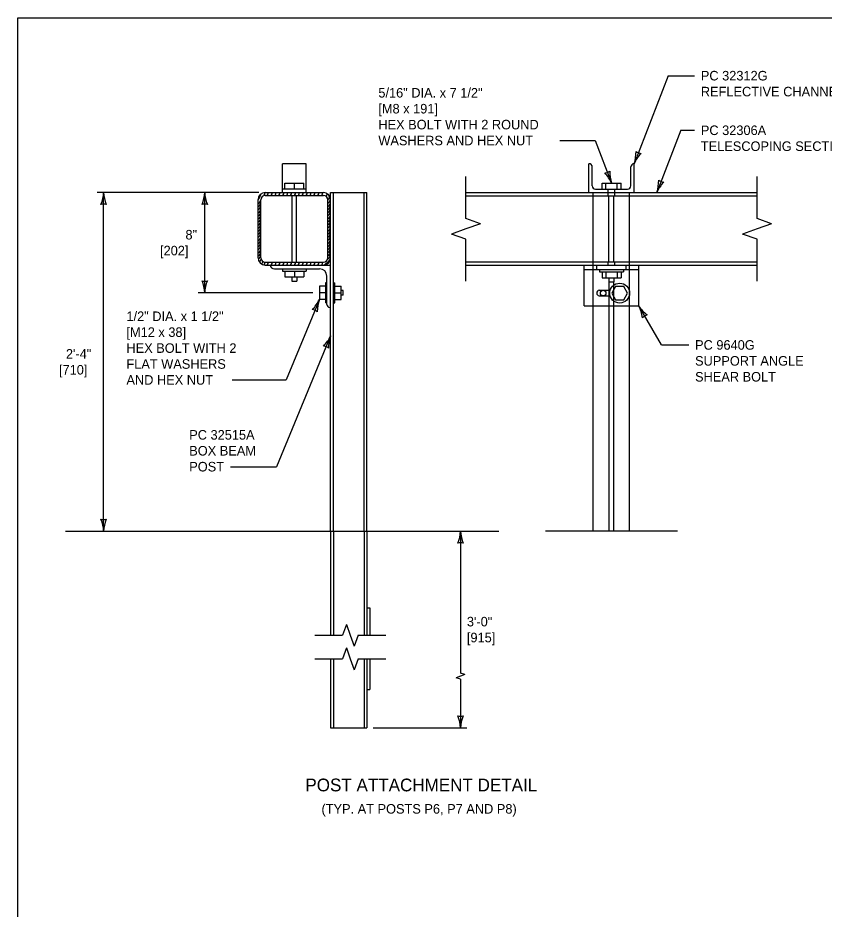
# Model space of a CAD drawing. Extents: x 49991.4 to 50021, y 49987.6 to 50011.4.
# Drawn here: x 49999.38 to 50004.45, y 49993.4 to 49999 of the extents above; entities that cross this region are included whole.
import ezdxf

# ---------------------------------------------------------------- set-up
doc = ezdxf.new("R2010")
doc.units = 0
for name, color, linetype in [('Level 1', 7, 'Continuous'), ('Level 2', 7, 'Continuous'), ('Level 3', 7, 'Continuous'), ('Level 4', 7, 'Continuous'), ('Level 6', 7, 'Continuous')]:
    doc.layers.add(name, color=color, linetype=linetype)

msp = doc.modelspace()

# ---------------------------------------------------------------- linework, layer by layer
at = {"layer": 'Level 1'}
for p, q in [((50001.0456, 49997.9021), (50001.0456, 49998.0824)), ((50001.1955, 49998.0824), (50001.0456, 49998.0824)), ((50001.1955, 49997.9021), (50001.1955, 49998.0824)), ((50002.9708, 49997.902), (50002.9708, 49998.0824)), ((50003.2538, 49998.0824), (50003.2546, 49998.0824)), ((50003.2546, 49997.902), (50003.2546, 49998.0824)), ((50002.9916, 49997.9428), (50002.9916, 49998.0624)), ((50003.2338, 49997.9428), (50003.2338, 49998.0624)), ((50003.0116, 49997.9228), (50003.2138, 49997.9228)), ((50003.0528, 49997.9228), (50003.0528, 49997.9596)), ((50003.0528, 49997.9596), (50003.1726, 49997.9596)), ((50003.0772, 49997.9228), (50003.0772, 49997.9596)), ((50003.148, 49997.9228), (50003.148, 49997.9596)), ((50003.1726, 49997.9228), (50003.1726, 49997.9596)), ((50000.9377, 49997.9021), (50001.3025, 49997.9021)), ((50000.9378, 49997.8839), (50001.3026, 49997.8839)), ((50001.1057, 49997.4643), (50001.1057, 49997.8839)), ((50001.1344, 49997.4643), (50001.1344, 49997.8839)), ((50001.3481, 49995.7737), (50001.3481, 49997.9021)), ((50001.3481, 49997.9021), (50001.5762, 49997.9021)), ((50001.3664, 49995.7737), (50001.3664, 49997.9021)), ((50001.558, 49995.7737), (50001.558, 49997.9021)), ((50001.5762, 49995.7737), (50001.5762, 49997.9021)), ((50002.198, 49997.902), (50004.0265, 49997.902)), ((50000.8921, 49997.4915), (50000.8921, 49997.8565)), ((50000.9104, 49997.4917), (50000.9104, 49997.8565)), ((50001.33, 49997.4917), (50001.33, 49997.8565)), ((50000.9377, 49997.4459), (50001.3481, 49997.4459)), ((50000.9378, 49997.4643), (50001.3026, 49997.4643)), ((50000.9954, 49997.4223), (50001.279, 49997.4223)), ((50001.0456, 49997.4223), (50001.0456, 49997.4081)), ((50001.1948, 49997.4223), (50001.1948, 49997.4081)), ((50002.198, 49997.4448), (50004.0265, 49997.4448)), ((50002.9406, 49997.1894), (50002.9406, 49997.4448)), ((50002.9406, 49997.4174), (50003.2834, 49997.4174)), ((50003.0373, 49997.4174), (50003.0373, 49997.4033)), ((50003.1868, 49997.4174), (50003.1868, 49997.4033)), ((50003.2834, 49997.1894), (50003.2834, 49997.4448)), ((50001.0456, 49997.4081), (50001.1948, 49997.4081)), ((50001.061, 49997.4081), (50001.061, 49997.3714)), ((50001.061, 49997.3714), (50001.1806, 49997.3714)), ((50001.1202, 49997.4081), (50001.1202, 49997.3714)), ((50001.1806, 49997.4081), (50001.1806, 49997.3714)), ((50001.3246, 49997.1981), (50001.3246, 49997.3767)), ((50003.0373, 49997.4033), (50003.1868, 49997.4033)), ((50003.0528, 49997.4033), (50003.0528, 49997.3664)), ((50003.0528, 49997.3664), (50003.1726, 49997.3664)), ((50003.0772, 49997.4033), (50003.0772, 49997.3664)), ((50003.148, 49997.4033), (50003.148, 49997.3664)), ((50003.1726, 49997.4033), (50003.1726, 49997.3664)), ((50001.3152, 49997.3133), (50001.2773, 49997.3133)), ((50001.2773, 49997.3133), (50001.2773, 49997.2295)), ((50001.3152, 49997.3335), (50001.3152, 49997.2091)), ((50001.3246, 49997.3335), (50001.3152, 49997.3335)), ((50001.3664, 49997.3335), (50001.3756, 49997.3335)), ((50001.3756, 49997.2091), (50001.3756, 49997.3335)), ((50001.3756, 49997.3133), (50001.4135, 49997.3133)), ((50001.4135, 49997.2295), (50001.4135, 49997.3133)), ((50001.3152, 49997.2713), (50001.2773, 49997.2713)), ((50001.3756, 49997.2713), (50001.4135, 49997.2713)), ((50001.427, 49997.2861), (50001.4135, 49997.2861)), ((50001.427, 49997.2569), (50001.4135, 49997.2569)), ((50001.427, 49997.2569), (50001.427, 49997.2861)), ((50003.035, 49997.2871), (50003.1037, 49997.2871)), ((50003.0352, 49997.2523), (50003.1037, 49997.2523)), ((50001.3152, 49997.2295), (50001.2773, 49997.2295)), ((50001.3246, 49997.2091), (50001.3152, 49997.2091)), ((50001.3664, 49997.2091), (50001.3756, 49997.2091)), ((50001.3756, 49997.2295), (50001.4135, 49997.2295)), ((50002.9406, 49997.1894), (50003.2834, 49997.1894)), ((50002.9977, 49995.7737), (50002.9977, 49997.1894)), ((50003.2262, 49995.7737), (50003.2262, 49997.1894)), ((50001.3481, 49997.1799), (50001.3428, 49997.1799)), ((49999.6824, 49995.7737), (50002.404, 49995.7737)), ((50003.5262, 49995.7737), (50002.6977, 49995.7737))]:
    msp.add_line(p, q, dxfattribs=at)
for points in [[(49999.3835, 49998.9992), (50016.7501, 49998.9992), (50016.7501, 49987.7988), (49999.3835, 49987.7988)], [(50003.1374, 49997.2278), (50003.19, 49997.2278), (50003.2131, 49997.2696), (50003.19, 49997.3118), (50003.1374, 49997.3118), (50003.1142, 49997.2696)]]:
    msp.add_lwpolyline(points, close=True, dxfattribs=at)
for points in [[(50000.8921, 49997.8565), (50000.9014, 49997.8691), (50000.9054, 49997.8777), (50000.9113, 49997.8937)], [(50000.9287, 49997.8823), (50000.9311, 49997.8855), (50000.9346, 49997.8922), (50000.935, 49997.902)], [(50000.95, 49997.8839), (50000.9558, 49997.8929), (50000.9556, 49997.9021)], [(50000.9744, 49997.8839), (50000.9802, 49997.8929), (50000.98, 49997.9021)], [(50000.9988, 49997.8839), (50001.0046, 49997.8929), (50001.0044, 49997.9021)], [(50001.0232, 49997.8839), (50001.0291, 49997.8929), (50001.0289, 49997.9021)], [(50001.0477, 49997.8839), (50001.0535, 49997.8929), (50001.0533, 49997.9021)], [(50001.0721, 49997.8839), (50001.0779, 49997.8929), (50001.0777, 49997.9021)], [(50001.0965, 49997.8839), (50001.1023, 49997.8929), (50001.1021, 49997.9021)], [(50001.1209, 49997.8839), (50001.1268, 49997.8929), (50001.1266, 49997.9021)], [(50001.1454, 49997.8839), (50001.1512, 49997.8929), (50001.151, 49997.9021)], [(50001.1698, 49997.8839), (50001.1756, 49997.8929), (50001.1754, 49997.9021)], [(50001.1942, 49997.8839), (50001.2, 49997.8929), (50001.1998, 49997.9021)], [(50001.2186, 49997.8839), (50001.2245, 49997.8929), (50001.2243, 49997.9021)], [(50001.2431, 49997.8839), (50001.2489, 49997.8929), (50001.2487, 49997.9021)], [(50001.2675, 49997.8839), (50001.2733, 49997.8929), (50001.2731, 49997.9021)], [(50001.2919, 49997.8839), (50001.2977, 49997.8929), (50001.2975, 49997.9021)], [(50001.3194, 49997.8781), (50001.3254, 49997.8874), (50001.3252, 49997.896)], [(50001.33, 49997.853), (50001.3401, 49997.8685), (50001.3398, 49997.8828)], [(50000.8921, 49997.8328), (50000.902, 49997.8392), (50000.9062, 49997.8477), (50000.9104, 49997.856)], [(50000.8921, 49997.8134), (50000.902, 49997.8199), (50000.9062, 49997.8284), (50000.9104, 49997.8366)], [(50000.8921, 49997.7941), (50000.902, 49997.8005), (50000.9062, 49997.809), (50000.9104, 49997.8173)], [(50001.33, 49997.8336), (50001.3397, 49997.84), (50001.3439, 49997.8485), (50001.3481, 49997.8567)], [(50001.33, 49997.8143), (50001.3397, 49997.8207), (50001.3439, 49997.8292), (50001.3481, 49997.8374)], [(50001.33, 49997.7949), (50001.3397, 49997.8013), (50001.3439, 49997.8098), (50001.3481, 49997.8181)], [(50000.8921, 49997.7747), (50000.902, 49997.7812), (50000.9062, 49997.7897), (50000.9104, 49997.7979)], [(50000.8921, 49997.7554), (50000.902, 49997.7619), (50000.9062, 49997.7704), (50000.9104, 49997.7786)], [(50000.8921, 49997.736), (50000.902, 49997.7425), (50000.9062, 49997.751), (50000.9104, 49997.7593)], [(50001.33, 49997.7756), (50001.3397, 49997.782), (50001.3439, 49997.7905), (50001.3481, 49997.7987)], [(50001.33, 49997.7562), (50001.3397, 49997.7626), (50001.3439, 49997.7711), (50001.3481, 49997.7794)], [(50001.33, 49997.7369), (50001.3397, 49997.7433), (50001.3439, 49997.7518), (50001.3481, 49997.76)], [(50000.8921, 49997.7167), (50000.902, 49997.7232), (50000.9062, 49997.7317), (50000.9104, 49997.7399)], [(50000.8921, 49997.6973), (50000.902, 49997.7038), (50000.9062, 49997.7123), (50000.9104, 49997.7206)], [(50000.8921, 49997.678), (50000.902, 49997.6845), (50000.9062, 49997.693), (50000.9104, 49997.7012)], [(50001.33, 49997.7175), (50001.3397, 49997.7239), (50001.3439, 49997.7324), (50001.3481, 49997.7407)], [(50001.33, 49997.6982), (50001.3397, 49997.7046), (50001.3439, 49997.7131), (50001.3481, 49997.7213)], [(50001.33, 49997.6788), (50001.3397, 49997.6852), (50001.3439, 49997.6937), (50001.3481, 49997.702)], [(50000.8921, 49997.6586), (50000.902, 49997.6651), (50000.9062, 49997.6736), (50000.9104, 49997.6819)], [(50000.8921, 49997.6393), (50000.902, 49997.6458), (50000.9062, 49997.6543), (50000.9104, 49997.6625)], [(50000.8921, 49997.6199), (50000.902, 49997.6264), (50000.9062, 49997.6349), (50000.9104, 49997.6432)], [(50001.33, 49997.6595), (50001.3397, 49997.6659), (50001.3439, 49997.6744), (50001.3481, 49997.6826)], [(50001.33, 49997.6401), (50001.3397, 49997.6465), (50001.3439, 49997.655), (50001.3481, 49997.6633)], [(50001.33, 49997.6208), (50001.3397, 49997.6272), (50001.3439, 49997.6357), (50001.3481, 49997.6439)], [(50000.8921, 49997.6006), (50000.902, 49997.6071), (50000.9062, 49997.6156), (50000.9104, 49997.6238)], [(50000.8921, 49997.5812), (50000.902, 49997.5877), (50000.9062, 49997.5962), (50000.9104, 49997.6045)], [(50000.8921, 49997.5619), (50000.902, 49997.5684), (50000.9062, 49997.5769), (50000.9104, 49997.5851)], [(50001.33, 49997.6014), (50001.3397, 49997.6078), (50001.3439, 49997.6163), (50001.3481, 49997.6246)], [(50001.33, 49997.5821), (50001.3397, 49997.5885), (50001.3439, 49997.597), (50001.3481, 49997.6052)], [(50001.33, 49997.5627), (50001.3397, 49997.5691), (50001.3439, 49997.5776), (50001.3481, 49997.5859)], [(50000.8921, 49997.5425), (50000.902, 49997.549), (50000.9062, 49997.5575), (50000.9104, 49997.5658)], [(50000.8921, 49997.5232), (50000.902, 49997.5297), (50000.9062, 49997.5382), (50000.9104, 49997.5464)], [(50000.8921, 49997.5038), (50000.902, 49997.5103), (50000.9062, 49997.5188), (50000.9104, 49997.5271)], [(50001.33, 49997.5434), (50001.3397, 49997.5498), (50001.3439, 49997.5583), (50001.3481, 49997.5665)], [(50001.33, 49997.5241), (50001.3397, 49997.5304), (50001.3439, 49997.5389), (50001.3481, 49997.5472)], [(50001.33, 49997.5047), (50001.3397, 49997.5111), (50001.3439, 49997.5196), (50001.3481, 49997.5278)], [(50000.8926, 49997.4848), (50000.902, 49997.491), (50000.9062, 49997.4995), (50000.9104, 49997.5077)], [(50000.8996, 49997.4664), (50000.9054, 49997.4702), (50000.9096, 49997.4787), (50000.9118, 49997.483)], [(50000.9115, 49997.4542), (50000.9174, 49997.458), (50000.9216, 49997.4665), (50000.9227, 49997.4688)], [(50001.3051, 49997.4459), (50001.3254, 49997.4623), (50001.3326, 49997.467), (50001.3481, 49997.4836)], [(50001.3291, 49997.4848), (50001.3397, 49997.4917), (50001.3439, 49997.5002), (50001.3481, 49997.5085)], [(50000.9303, 49997.4465), (50000.9312, 49997.4477), (50000.9347, 49997.4544), (50000.9351, 49997.4644)], [(50000.9499, 49997.4459), (50000.9559, 49997.4551), (50000.9557, 49997.4643)], [(50000.9744, 49997.4459), (50000.9803, 49997.4551), (50000.9801, 49997.4643)], [(50000.9988, 49997.4459), (50001.0047, 49997.4551), (50001.0045, 49997.4643)], [(50001.0232, 49997.4459), (50001.0292, 49997.4551), (50001.029, 49997.4643)], [(50001.0476, 49997.4459), (50001.0536, 49997.4551), (50001.0534, 49997.4643)], [(50001.0721, 49997.4459), (50001.078, 49997.4551), (50001.0778, 49997.4643)], [(50001.0965, 49997.4459), (50001.1024, 49997.4551), (50001.1022, 49997.4643)], [(50001.1209, 49997.4459), (50001.1269, 49997.4551), (50001.1267, 49997.4643)], [(50001.1453, 49997.4459), (50001.1513, 49997.4551), (50001.1511, 49997.4643)], [(50001.1698, 49997.4459), (50001.1757, 49997.4551), (50001.1755, 49997.4643)], [(50001.1942, 49997.4459), (50001.2001, 49997.4551), (50001.1999, 49997.4643)], [(50001.2186, 49997.4459), (50001.2246, 49997.4551), (50001.2244, 49997.4643)], [(50001.243, 49997.4459), (50001.249, 49997.4551), (50001.2488, 49997.4643)], [(50001.2675, 49997.4459), (50001.2734, 49997.4551), (50001.2732, 49997.4643)], [(50001.2919, 49997.4459), (50001.2978, 49997.4551), (50001.2976, 49997.4643)], [(50001.1042, 49997.3714), (50001.1042, 49997.3449)], [(50001.136, 49997.3714), (50001.136, 49997.3449)], [(50003.0961, 49997.3664), (50003.0961, 49997.3398)], [(50003.1279, 49997.3664), (50003.1279, 49997.3398)], [(50001.1042, 49997.3449), (50001.136, 49997.3449)], [(50003.0961, 49997.3398), (50003.1279, 49997.3398)]]:
    msp.add_lwpolyline(points, dxfattribs=at)
for centre, radius in [((50003.1637, 49997.2697), 0.0624), ((50003.0603, 49997.2697), 0.0174)]:
    msp.add_circle(centre, radius, dxfattribs=at)
for centre, radius, start, end in [((50002.9716, 49998.0624), 0.02, 0, 92.2906), ((50003.2538, 49998.0624), 0.02, 90, 180), ((50003.0116, 49997.9428), 0.02, 180, 270), ((50003.2138, 49997.9428), 0.02, 270, 0), ((50000.9377, 49997.8565), 0.0456, 90, 180), ((50000.9378, 49997.8565), 0.0274, 90, 180), ((50001.3025, 49997.8565), 0.0456, 0, 90), ((50001.3026, 49997.8565), 0.0274, 0, 90), ((50000.9377, 49997.4915), 0.0456, 180, 270), ((50000.9378, 49997.4917), 0.0274, 180, 270), ((50001.3025, 49997.4915), 0.0456, 270, 0), ((50001.3026, 49997.4917), 0.0274, 270, 0), ((50000.9954, 49997.4497), 0.0274, 187.907, 270), ((50001.279, 49997.3767), 0.0456, 0, 90), ((50003.0376, 49997.2697), 0.0176, 98.4952, 262.0182), ((50001.3428, 49997.1981), 0.0182, 180, 270)]:
    msp.add_arc(centre, radius, start, end, dxfattribs=at)
at = {"layer": 'Level 3'}
for p, q in [((49999.9224, 49995.7737), (49999.9224, 49997.9021)), ((50000.5571, 49997.2714), (50000.5571, 49997.9021)), ((50002.164, 49994.8632), (50002.1366, 49994.8535)), ((50002.164, 49994.8438), (50002.1366, 49994.8535)), ((50002.1914, 49994.8729), (50002.164, 49994.8826)), ((50002.1914, 49994.8729), (50002.164, 49994.8632))]:
    msp.add_line(p, q, dxfattribs=at)
for points in [[(50003.4692, 49998.6357), (50003.2546, 49998.0824)], [(50003.4692, 49998.6357), (50003.6335, 49998.6357)], [(50003.5485, 49998.2927), (50003.3971, 49997.902)], [(50003.5485, 49998.2927), (50003.6335, 49998.2927)], [(50002.7871, 49998.2283), (50003.0107, 49998.2283)], [(50003.0107, 49998.2283), (50003.1127, 49997.9596)], [(50000.8977, 49997.9021), (49999.8824, 49997.9021)], [(50001.2373, 49997.2714), (50000.5171, 49997.2714)], [(50001.2773, 49997.2295), (50001.0682, 49996.7243)], [(50003.4272, 49996.944), (50003.2834, 49997.1894)], [(50001.3481, 49997.0007), (50001.008, 49996.179)], [(50003.4272, 49996.944), (50003.5972, 49996.944)], [(50000.7297, 49996.7243), (50001.0682, 49996.7243)], [(50000.7194, 49996.1791), (50001.008, 49996.179)], [(50002.164, 49995.7737), (50002.164, 49994.8826)], [(50002.164, 49994.8438), (50002.164, 49994.5375)], [(50001.6162, 49994.5375), (50002.204, 49994.5375)]]:
    msp.add_lwpolyline(points, dxfattribs=at)
for centre, radius, start, end in [((50003.0335, 49998.1558), 0.233, 341.6311, 0.8809), ((50003.4584, 49997.9935), 0.2223, 136.2598, 156.4433), ((50003.301, 49998.2019), 0.0548, 230.9426, 266.6649), ((50003.0672, 49998.0795), 0.0548, 272.9312, 308.6536), ((50003.3236, 49998.0299), 0.2223, 178.2484, 198.4319), ((50002.8992, 49997.8662), 0.233, 23.6197, 42.8696), ((50003.1759, 49997.9753), 0.233, 341.6554, 0.9053), ((50003.4434, 49998.0216), 0.0548, 230.967, 266.6893), ((50003.6009, 49997.8132), 0.2223, 136.2841, 156.4677), ((49999.7003, 49997.9113), 0.2223, 337.456, 357.6395), ((50000.1551, 49997.9136), 0.233, 182.8273, 202.0772), ((50000.335, 49997.9113), 0.2223, 337.456, 357.6395), ((50000.7898, 49997.9136), 0.233, 182.8273, 202.0772), ((49999.9224, 49997.7739), 0.0548, 72.1388, 107.8612), ((50000.5571, 49997.7739), 0.0548, 72.1388, 107.8612), ((50000.5571, 49997.3996), 0.0548, 252.1388, 287.8612), ((50000.3244, 49997.2599), 0.233, 2.8273, 22.0772), ((50000.7792, 49997.2622), 0.2223, 157.456, 177.6395), ((50001.0756, 49997.3229), 0.2223, 314.9721, 335.1556), ((50001.4967, 49997.1511), 0.233, 160.3434, 179.5933), ((50003.0871, 49997.085), 0.2223, 7.8256, 28.0091), ((50003.4784, 49997.317), 0.233, 213.1969, 232.4467), ((50001.2283, 49997.111), 0.0548, 49.6549, 85.3773), ((50003.3482, 49997.0788), 0.0548, 102.5084, 138.2307), ((50001.1464, 49997.0941), 0.2223, 314.9733, 335.1569), ((50001.5675, 49996.9223), 0.233, 160.3446, 179.5945), ((50001.2991, 49996.8822), 0.0548, 49.6562, 85.3785), ((49999.9224, 49995.9019), 0.0548, 252.1388, 287.8612), ((49999.6897, 49995.7622), 0.233, 2.8273, 22.0772), ((50000.1445, 49995.7645), 0.2223, 157.456, 177.6395), ((50001.9419, 49995.7829), 0.2223, 337.456, 357.6395), ((50002.3967, 49995.7852), 0.233, 182.8273, 202.0772), ((50002.164, 49995.6455), 0.0548, 72.1388, 107.8612), ((50002.164, 49994.6657), 0.0548, 252.1388, 287.8612), ((50001.9313, 49994.526), 0.233, 2.8273, 22.0772), ((50002.3861, 49994.5283), 0.2223, 157.456, 177.6395)]:
    msp.add_arc(centre, radius, start, end, dxfattribs=at)
at = {"layer": 'Level 4'}
for p, q in [((50001.1955, 49997.9228), (50001.0456, 49997.9228)), ((50001.0608, 49997.9228), (50001.0608, 49997.9597)), ((50001.0608, 49997.9597), (50001.1806, 49997.9597)), ((50001.1206, 49997.9228), (50001.1206, 49997.9597)), ((50001.1806, 49997.9228), (50001.1806, 49997.9597)), ((50003.0907, 49997.8814), (50003.0907, 49997.9228)), ((50003.1332, 49997.8814), (50003.1332, 49997.9228)), ((50002.198, 49997.8814), (50004.0265, 49997.8814)), ((50002.9977, 49997.1894), (50002.9977, 49997.902)), ((50003.0961, 49997.4657), (50003.0961, 49997.8814)), ((50003.1279, 49997.4657), (50003.1279, 49997.8814)), ((50003.2262, 49997.1894), (50003.2262, 49997.902)), ((50002.198, 49997.4657), (50004.0265, 49997.4657)), ((50003.0907, 49997.4448), (50003.0907, 49997.4657)), ((50003.1332, 49997.4448), (50003.1332, 49997.4657)), ((50003.02, 49997.4174), (50003.02, 49997.4448)), ((50003.2052, 49997.4174), (50003.2052, 49997.4448)), ((50003.0978, 49995.7737), (50003.0978, 49997.3398)), ((50003.1262, 49995.7737), (50003.1262, 49997.3398)), ((50001.3481, 49995.7737), (50001.3481, 49995.1198)), ((50001.3664, 49995.7737), (50001.3664, 49995.1198)), ((50001.558, 49995.7737), (50001.558, 49995.1198)), ((50001.5762, 49995.7737), (50001.5762, 49995.1198)), ((50001.5762, 49995.2924), (50001.5953, 49995.2924)), ((50001.5953, 49995.2924), (50001.5953, 49995.1198)), ((50001.3481, 49994.972), (50001.3481, 49994.5375)), ((50001.3663, 49994.972), (50001.3663, 49994.5375)), ((50001.558, 49994.972), (50001.558, 49994.5375)), ((50001.5762, 49994.972), (50001.5762, 49994.5375)), ((50001.5953, 49994.972), (50001.5953, 49994.7782)), ((50001.5762, 49994.7782), (50001.5953, 49994.7782)), ((50001.3481, 49994.5375), (50001.5762, 49994.5375))]:
    msp.add_line(p, q, dxfattribs=at)
at = {"layer": 'Level 6'}
for p, q in [((50002.198, 49997.7382), (50002.198, 49998.002)), ((50004.0265, 49997.7382), (50004.0265, 49998.002)), ((50002.2894, 49997.7058), (50002.198, 49997.7382)), ((50002.2894, 49997.7058), (50002.198, 49997.6734)), ((50004.1179, 49997.7058), (50004.0265, 49997.7382)), ((50004.1179, 49997.7058), (50004.0265, 49997.6734)), ((50002.198, 49997.6734), (50002.1066, 49997.641)), ((50002.198, 49997.6086), (50002.1066, 49997.641)), ((50004.0265, 49997.6734), (50003.9351, 49997.641)), ((50004.0265, 49997.6086), (50003.9351, 49997.641)), ((50002.198, 49997.3448), (50002.198, 49997.6086)), ((50004.0265, 49997.3448), (50004.0265, 49997.6086)), ((50001.4474, 49995.1884), (50001.4231, 49995.1198)), ((50001.4474, 49995.1884), (50001.4717, 49995.1198)), ((50001.2481, 49995.1198), (50001.4231, 49995.1198)), ((50001.4717, 49995.1198), (50001.496, 49995.0512)), ((50001.5203, 49995.1198), (50001.496, 49995.0512)), ((50001.5203, 49995.1198), (50001.6953, 49995.1198)), ((50001.4474, 49995.0406), (50001.4231, 49994.972)), ((50001.4474, 49995.0406), (50001.4717, 49994.972)), ((50001.2481, 49994.972), (50001.4231, 49994.972)), ((50001.4717, 49994.972), (50001.496, 49994.9034)), ((50001.5203, 49994.972), (50001.496, 49994.9034)), ((50001.5203, 49994.972), (50001.6953, 49994.972))]:
    msp.add_line(p, q, dxfattribs=at)

# ---------------------------------------------------------------- texts
at = {"layer": 'Level 2'}
for s, height, p in [('PC 32312G', 0.06, (50003.6735, 49998.6057)), ('5/16" DIA. x 7 1/2"', 0.06, (50001.6479, 49998.4983)), ('REFLECTIVE CHANNEL', 0.06, (50003.6735, 49998.5057)), ('[M8 x 191]', 0.06, (50001.6479, 49998.3983)), ('HEX BOLT WITH 2 ROUND', 0.06, (50001.6479, 49998.2983)), ('PC 32306A', 0.06, (50003.6735, 49998.2627)), ('WASHERS AND HEX NUT', 0.06, (50001.6479, 49998.1983)), ('TELESCOPING SECTION x 24\'-0"', 0.06, (50003.6735, 49998.1627)), ('8"', 0.06, (50000.4364, 49997.6067)), ('[202]', 0.06, (50000.2767, 49997.5068)), ('1/2" DIA. x 1 1/2"', 0.06, (50000.0657, 49997.0943)), ('[M12 x 38]', 0.06, (50000.0657, 49996.9943)), ('PC 9640G', 0.06, (50003.6372, 49996.914)), ('2\'-4"', 0.06, (49999.6855, 49996.8579)), ('HEX BOLT WITH 2', 0.06, (50000.0657, 49996.8943)), ('FLAT WASHERS', 0.06, (50000.0657, 49996.7943)), ('SUPPORT ANGLE ', 0.06, (50003.6372, 49996.814)), ('[710]', 0.06, (49999.642, 49996.7579)), ('AND HEX NUT', 0.06, (50000.0657, 49996.6943)), ('SHEAR BOLT', 0.06, (50003.6372, 49996.714)), ('PC 32515A', 0.06, (50000.4602, 49996.3491)), ('BOX BEAM ', 0.06, (50000.4602, 49996.2491)), ('POST', 0.06, (50000.4602, 49996.1491)), ('3\'-0"', 0.06, (50002.204, 49995.1756)), ('[915]', 0.06, (50002.204, 49995.0756)), ('POST ATTACHMENT DETAIL', 0.08, (50001.1896, 49994.1393)), ('(TYP. AT POSTS P6, P7 AND P8)', 0.06, (50001.2908, 49993.9993))]:
    msp.add_text(s, height=height, dxfattribs=at).set_placement(p)

doc.saveas('drawing.dxf')
